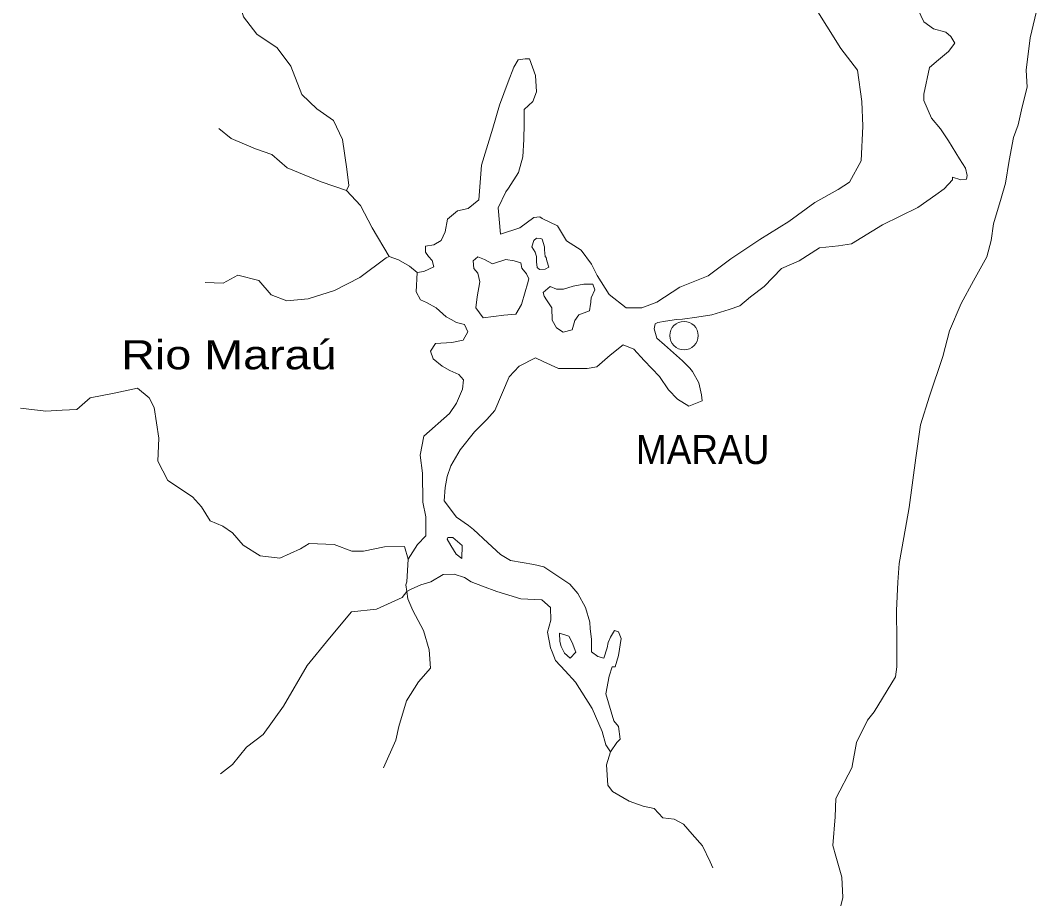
# Model space of a CAD drawing. Extents: x 47169 to 972804, y 7447977 to 9608469.
# Drawn here: x 482300 to 505509, y 8427856 to 8447860 of the extents above; entities that cross this region are included whole.
import ezdxf

# ---------------------------------------------------------------- set-up
doc = ezdxf.new("R2010")
doc.units = 0
doc.header["$LTSCALE"] = 270
doc.layers.add('1', color=7, linetype='Continuous', lineweight=13)
doc.layers.add('2', color=7, linetype='Continuous', lineweight=13)
doc.layers.add('3', color=7, linetype='Continuous')

msp = doc.modelspace()

# ---------------------------------------------------------------- linework, layer by layer
at = {"layer": '1'}
for points in [[(489724, 8443984.4), (489777.9, 8444095.1), (489734.6, 8444471.1), (489637.1, 8445145.7), (489431.8, 8445576.9), (489053.8, 8445842.2), (488708.2, 8446173.8), (488459.5, 8446815.2), (488146.2, 8447235.3), (487681.8, 8447544.8), (487379.2, 8447942.8), (487271.1, 8448318.8), (486925.4, 8448738.9), (486406.9, 8449015.1), (486190.9, 8449125.6), (485996.3, 8449413), (485607.6, 8449468.1), (485391.6, 8449468)], [(504006.8, 8441929.1), (504309.2, 8442471), (504406.4, 8442847), (504460.4, 8443223), (504633.3, 8443809.2), (504730.5, 8444152), (504817, 8444671.8), (504914.2, 8445191.6), (505022.2, 8445479.1), (505108.7, 8445888.3), (505227.6, 8446341.7), (505206, 8446728.8), (505292.6, 8447458.7), (505508.7, 8448365.6)], [(502733.6, 8448111.7), (502874, 8447824.1), (503089.9, 8447669.2), (503370.6, 8447591.8), (503489.4, 8447492.2), (503575.8, 8447337.4), (503435.4, 8447149.4), (503208.6, 8446961.4), (503003.4, 8446784.5), (502873.8, 8446176.2), (502873.8, 8446032.4), (503046.5, 8445634.2), (503251.6, 8445390.9), (503435.1, 8445114.4), (503683.3, 8444705.2), (503823.7, 8444495), (503856, 8444329.1), (503845.2, 8444240.6), (503715.7, 8444229.6), (503521.3, 8444284.9), (503521.3, 8444229.6), (503337.8, 8444019.5), (503143.4, 8443886.8), (502733.2, 8443599.3), (501934.2, 8443201.2), (501221.7, 8442769.9), (500930.2, 8442725.7), (500498.4, 8442681.5), (500034.2, 8442382.9), (499634.8, 8442205.9), (499235.3, 8441796.7), (498922.3, 8441564.4), (498684.8, 8441354.3), (498436.5, 8441276.8), (498047.9, 8441155.2), (497702.5, 8441099.8), (497378.7, 8441055.6), (497238.3, 8441044.5), (496990, 8441011.3), (496817.3, 8440978.1), (496752.6, 8440944.9), (496731, 8440834.3), (496795.8, 8440624.2), (496968.5, 8440469.3), (497378.8, 8440104.4), (497540.7, 8439938.6), (497605.5, 8439861.1), (497745.8, 8439606.8), (497810.6, 8439330.3), (497821.4, 8439197.6), (497519.2, 8439075.9), (497260.1, 8439230.7), (497055, 8439440.8), (496849.9, 8439750.4), (496504.4, 8440115.4), (496266.9, 8440369.7), (496029.4, 8440469.2), (495727.2, 8440236.9), (495425, 8439971.4), (495209.1, 8439927.2), (494550.7, 8439927), (494205.2, 8440092.8), (494032.5, 8440170.2), (493654.7, 8439982.1), (493428.1, 8439738.7), (493104.5, 8438975.5), (492921, 8438765.3), (492640.5, 8438488.8), (492316.8, 8438079.4), (492101, 8437714.4), (492014.8, 8437471.1), (491971.7, 8437216.7), (491950.2, 8436918.1), (492230.9, 8436542.1), (492500.8, 8436354.2), (492619.5, 8436265.7)], [(492800.7, 8444560.6), (493059.5, 8445401.2), (493210.6, 8445932.1), (493404.8, 8446463.1), (493534.2, 8446794.9), (493631.4, 8446960.8), (493793.3, 8446983), (493890.5, 8446983), (494031, 8446607), (494052.6, 8446231), (493966.3, 8446009.7), (493772, 8445832.8), (493772.1, 8445500.9), (493761.4, 8445147), (493739.9, 8444748.9), (493642.8, 8444394.9), (493416.2, 8444041), (493351.4, 8443952.5), (493178.8, 8443587.5), (493232.9, 8442990.2), (493675.5, 8443134.2), (493988.5, 8443366.5), (494128.9, 8443388.6), (494182.9, 8443344.4), (494528.4, 8443178.6), (494733.6, 8442835.8), (495068.3, 8442625.7), (495305.8, 8442305), (495435.4, 8442050.7), (495705.4, 8441619.4), (496094, 8441309.8), (496450.3, 8441309.8), (496795.7, 8441442.6), (497313.8, 8441785.5), (497961.5, 8442039.9), (498479.6, 8442427.1), (499138.1, 8442869.5), (499796.7, 8443278.7), (500390.5, 8443710), (500919.5, 8444008.6), (501178.6, 8444174.5), (501448.5, 8444661.1), (501480.9, 8445446.4), (501459.4, 8446010.4), (501362.2, 8446729.3), (500984.4, 8447216), (500660.4, 8447724.7), (500455.3, 8448056.5)], [(491333.2, 8442115.9), (491160.4, 8442259.7), (490912.1, 8442403.4), (490696.2, 8442480.7), (490307.3, 8443133.1), (490048, 8443641.7), (489724, 8443984.4), (489151.7, 8444183.3), (488374.2, 8444503.7), (488028.6, 8444802.1), (487650.7, 8444934.7), (487099.9, 8445166.7), (486819.1, 8445398.8)], [(492619.5, 8436265.7), (492943.4, 8435956.2), (493234.9, 8435690.8), (493461.6, 8435558.1), (493990.4, 8435469.8), (494217.1, 8435414.6), (494584.1, 8435171.3), (494810.7, 8435016.5), (494994.2, 8434806.4), (495167, 8434485.7), (495264.2, 8434153.9), (495275, 8433999.1), (495307.4, 8433766.8), (495307.5, 8433479.3), (495447.8, 8433368.7), (495588.1, 8433335.6), (495663.6, 8433567.8), (495685.1, 8433689.5), (495739.1, 8433811.2), (495825.4, 8433966), (495922.5, 8433932.9), (495976.5, 8433778), (495922.6, 8433390.9), (495847.1, 8433136.5), (495771.5, 8433136.5), (495706.8, 8432926.4), (495631.4, 8432517.2), (495814.9, 8431908.9), (495922.9, 8431776.2), (495955.3, 8431488.6), (495879.8, 8431411.2), (495739.5, 8431201.1), (495631.6, 8431355.9), (495545.2, 8431665.5), (495318.5, 8432185.3), (494940.7, 8432782.5), (494703.2, 8433047.8), (494487.3, 8433280.1), (494411.8, 8433479.1), (494368.6, 8433567.6), (494303.8, 8433921.5), (494379.2, 8434198), (494368.4, 8434485.6), (494174.1, 8434662.5), (493699.2, 8434684.5), (493148.8, 8434850.2), (492825, 8434971.8), (492565.9, 8435071.3), (492414.8, 8435170.8), (492177.4, 8435248.1), (491929.1, 8435237), (491648.6, 8435071), (491422, 8435004.5), (491195.4, 8434904.9), (491098.3, 8434849.6), (491076.6, 8435004.4), (491098.2, 8435070.8), (491130.4, 8435590.6), (491346.1, 8435922.5), (491529.5, 8436121.6), (491529.4, 8436552.9), (491464.5, 8436884.7), (491453.5, 8437548.3), (491399.4, 8437957.5), (491485.6, 8438388.9), (492068.3, 8438908.9), (492230.1, 8439141.2), (492370.4, 8439461.9), (492391.9, 8439672.1), (492283.9, 8439793.7), (492078.8, 8439882.1), (491906, 8439981.6), (491700.9, 8440147.4), (491636.1, 8440324.4), (491754.7, 8440501.4), (492121.8, 8440523.6), (492380.8, 8440579), (492488.7, 8440767), (492413.1, 8440932.9), (492229.6, 8440977.1), (492110.8, 8441043.4), (491992, 8441109.7), (491765.3, 8441308.7), (491549.3, 8441430.3), (491409, 8441496.6), (491311.8, 8441673.6), (491333.2, 8442115.9), (491484.3, 8442138.1), (491711, 8442248.8), (491678.6, 8442392.6), (491592.2, 8442481), (491527.4, 8442580.5), (491527.3, 8442713.2), (491710.8, 8442746.5), (491883.5, 8442846.1), (491969.8, 8443045.2), (492023.7, 8443332.8), (492250.4, 8443520.8), (492498.7, 8443576.2), (492736.1, 8443775.4), (492800.7, 8444560.6)], [(490696.2, 8442480.7), (490631.4, 8442447.5), (490027, 8442004.9), (489455, 8441706), (488850.6, 8441517.8), (488364.8, 8441473.3), (488008.5, 8441605.8), (487727.7, 8441937.5), (487252.6, 8442058.9), (486918.1, 8441870.8), (486507.9, 8441892.7)], [(495284.4, 8441398.1), (495262.8, 8441243.3), (495014.6, 8441154.8), (494928.2, 8441022), (494863.5, 8440811.9), (494658.4, 8440756.5), (494507.3, 8440856), (494410.1, 8441033), (494399.2, 8441309.4), (494280.5, 8441497.4), (494226.5, 8441574.8), (494204.9, 8441663.3), (494366.7, 8441796.1), (494507.1, 8441740.8), (494669, 8441740.8), (494884.9, 8441807.2), (495133.2, 8441851.5), (495273.5, 8441851.6), (495338.3, 8441851.6), (495381.5, 8441718.9), (495295.2, 8441541.9), (495284.4, 8441376)], [(500951.2, 8427573.8), (501026.8, 8427883.4), (501005.2, 8428347.9), (500865, 8428823.5), (500800.2, 8429066.8), (500854.2, 8429719.4), (500865, 8430139.7), (501242.7, 8430847.5), (501242.7, 8430869.6), (501339.8, 8431411.5), (501588, 8431920.3), (501739.1, 8432108.3), (502224.8, 8432904.5), (502257.2, 8433136.8), (502257.2, 8433734), (502246.5, 8434419.7), (502279, 8435061.2), (502311.4, 8435492.5), (502419.3, 8436078.7), (502538.1, 8436764.4), (502689.4, 8437892.5), (502797.4, 8438644.5), (503002.5, 8439297), (503304.9, 8440203.9), (503456.1, 8440790), (503726, 8441409.3), (504006.8, 8441929.1)], [(491130.4, 8435590.6), (491044, 8435878.1), (490590.7, 8435866.9), (490115.8, 8435767.2), (489846, 8435767.1), (489446.6, 8435921.8), (488874.6, 8435943.6), (488680.4, 8435821.9), (488205.6, 8435611.5), (487763.1, 8435666.6), (487374.4, 8435909.8), (487126.1, 8436186.1), (486910.1, 8436340.8), (486618.7, 8436462.3), (486424.2, 8436783), (486219, 8437004.1), (485657.6, 8437379.8), (485430.7, 8437822.1), (485452, 8438341.9), (485343.6, 8439038.6), (485235.5, 8439259.7), (484965.6, 8439480.8), (484436.7, 8439369.8), (483886.3, 8439258.9), (483584.2, 8438993.3), (483249.6, 8438982), (482882.6, 8438959.6), (482299.7, 8439025.6)], [(486859.1, 8430700.3), (487128.8, 8430910.6), (487452.3, 8431308.9), (487829.8, 8431596.6), (488293.5, 8432238.3), (488832.7, 8433167.6), (489339.6, 8433787.2), (489835.8, 8434384.6), (490407.7, 8434451.2), (490990.4, 8434716.8), (491098.3, 8434849.6)], [(491098.3, 8434849.6), (491119.9, 8434683.7), (491238.7, 8434418.3), (491476.3, 8433964.9), (491605.9, 8433522.6), (491638.5, 8433102.3), (491368.8, 8432792.6), (491088.4, 8432361.1), (490915.9, 8431774.9), (490851.3, 8431465.2), (490571, 8430834.7)], [(495739.5, 8431201.1), (495642.5, 8430902.4), (495674.9, 8430437.9), (495782.8, 8430294.2), (496160.5, 8430073), (496484.2, 8429962.5), (496732.4, 8429907.2), (496926.7, 8429697.1), (497185.6, 8429663.9), (497401.4, 8429553.4), (497595.7, 8429321.1), (497833.1, 8429055.7), (498005.7, 8428690.7), (498070.5, 8428558)]]:
    msp.add_lwpolyline(points, dxfattribs=at)
for points in [[(493988.7, 8442846.7), (494053.4, 8442902), (494150.6, 8442890.9), (494183, 8442879.9), (494237, 8442702.9), (494237, 8442636.6), (494247.8, 8442481.8), (494269.4, 8442459.6), (494291, 8442382.2), (494334.2, 8442238.5), (494247.9, 8442194.2), (494118.4, 8442183.1), (494064.4, 8442227.3), (494053.5, 8442360.1), (494053.5, 8442481.7), (494021.1, 8442581.2), (493945.5, 8442702.9)], [(493351.8, 8442415.2), (493546.2, 8442382.1), (493697.3, 8442337.8), (493718.9, 8442216.2), (493826.9, 8442083.5), (493880.9, 8441972.9), (493848.6, 8441862.3), (493794.6, 8441674.3), (493708.3, 8441386.7), (493578.9, 8441165.5), (493309, 8441143.3), (492834, 8441087.9), (492672, 8441309), (492704.4, 8441563.4), (492758.2, 8441906.3), (492715, 8442105.3), (492628.6, 8442204.8), (492607, 8442381.8), (492714.9, 8442470.3), (492866, 8442415.1), (493049.6, 8442315.6)], [(492252.7, 8435989.1), (492360.6, 8435900.7), (492349.9, 8435602.1), (492220.4, 8435701.6), (492101.6, 8435900.6), (492015.2, 8436044.4), (492036.8, 8436077.5), (492144.7, 8436077.6)], [(494789.4, 8433833.1), (494865, 8433689.3), (494951.3, 8433468.2), (494821.9, 8433335.4), (494692.3, 8433446), (494616.8, 8433600.8), (494584.4, 8433711.4), (494573.5, 8433899.4)]]:
    msp.add_lwpolyline(points, close=True, dxfattribs=at)
at = {"layer": '2'}
msp.add_circle((497411.1, 8440679.5), 323.8, dxfattribs=at)

# ---------------------------------------------------------------- texts
at = {"layer": '3'}
for s, width, p in [('Rio Maraú', 1.2, (484595.9, 8439912.2)), ('MARAU', 0.95, (496316.9, 8437754.6))]:
    msp.add_text(s, height=662.5, dxfattribs=dict(at, width=width)).set_placement(p)

doc.saveas('drawing.dxf')
